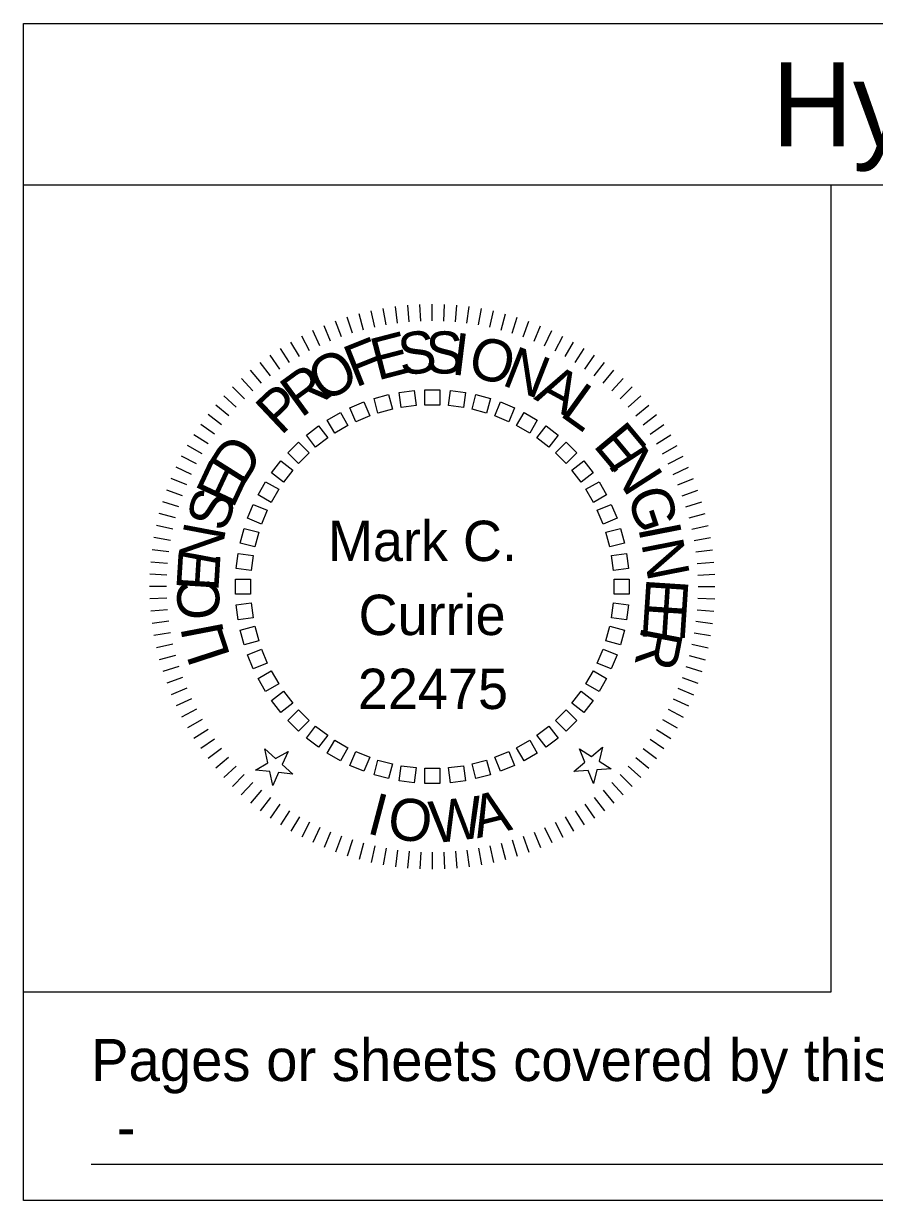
# Model space of a CAD drawing. Extents: x -0.84 to 4.97, y -1.01 to 2.42.
# Drawn here: x 4.3407 to 4.5514, y -0.9865 to -0.6948 of the extents above; entities that cross this region are included whole.
import ezdxf

# ---------------------------------------------------------------- set-up
doc = ezdxf.new("R2010")
doc.units = 0
for name, color, linetype in [('Level 1', 7, 'Continuous'), ('Level 2', 7, 'Continuous'), ('SheetGridMajor', 7, 'Continuous'), ('SheetGridMinor', 7, 'Continuous'), ('SheetText', 7, 'Continuous')]:
    doc.layers.add(name, color=color, linetype=linetype)

msp = doc.modelspace()

# ---------------------------------------------------------------- linework, layer by layer
at = {"layer": 'Level 1'}
for p, q in [((4.42489, -0.77078), (4.42381, -0.76675)), ((4.42768, -0.77009), (4.42678, -0.76603)), ((4.43049, -0.76953), (4.42977, -0.76543)), ((4.43333, -0.7691), (4.43279, -0.76497)), ((4.43619, -0.76878), (4.43583, -0.76463)), ((4.43906, -0.7686), (4.43887, -0.76443)), ((4.44193, -0.76853), (4.44193, -0.76437)), ((4.4448, -0.7686), (4.44498, -0.76443)), ((4.44766, -0.76878), (4.44803, -0.76463)), ((4.45052, -0.7691), (4.45106, -0.76497)), ((4.45336, -0.76953), (4.45408, -0.76543)), ((4.45618, -0.7701), (4.45708, -0.76603)), ((4.45897, -0.77078), (4.46004, -0.76675)), ((4.41673, -0.77355), (4.41514, -0.7697)), ((4.41941, -0.7725), (4.41799, -0.76859)), ((4.42213, -0.77158), (4.42088, -0.76761)), ((4.46172, -0.77158), (4.46298, -0.76761)), ((4.46444, -0.7725), (4.46587, -0.76859)), ((4.46712, -0.77355), (4.46871, -0.7697)), ((4.41153, -0.77597), (4.4096, -0.77228)), ((4.4141, -0.7747), (4.41234, -0.77093)), ((4.46975, -0.7747), (4.47151, -0.77093)), ((4.47232, -0.77597), (4.47425, -0.77228)), ((4.40655, -0.77884), (4.40432, -0.77533)), ((4.40901, -0.77735), (4.40693, -0.77375)), ((4.47484, -0.77735), (4.47693, -0.77375)), ((4.4773, -0.77884), (4.47954, -0.77533)), ((4.40417, -0.78044), (4.40178, -0.77703)), ((4.47969, -0.78044), (4.48208, -0.77703)), ((4.39961, -0.78394), (4.39693, -0.78074)), ((4.40185, -0.78214), (4.39931, -0.77883)), ((4.482, -0.78214), (4.48454, -0.77883)), ((4.48424, -0.78394), (4.48692, -0.78074)), ((4.39745, -0.78583), (4.39464, -0.78276)), ((4.4864, -0.78583), (4.48922, -0.78276)), ((4.39339, -0.78989), (4.39032, -0.78708)), ((4.39538, -0.78782), (4.39243, -0.78487)), ((4.48848, -0.78782), (4.49142, -0.78487)), ((4.49046, -0.78989), (4.49354, -0.78708)), ((4.3915, -0.79205), (4.3883, -0.78937)), ((4.49236, -0.79205), (4.49555, -0.78937)), ((4.3897, -0.79429), (4.38639, -0.79175)), ((4.49416, -0.79429), (4.49746, -0.79175)), ((4.388, -0.79661), (4.38459, -0.79422)), ((4.49585, -0.79661), (4.49927, -0.79422)), ((4.3864, -0.79899), (4.38289, -0.79676)), ((4.49745, -0.799), (4.50096, -0.79676)), ((4.38353, -0.80397), (4.37984, -0.80204)), ((4.38491, -0.80145), (4.38131, -0.79937)), ((4.49894, -0.80145), (4.50255, -0.79937)), ((4.50032, -0.80397), (4.50402, -0.80205)), ((4.38226, -0.80654), (4.37849, -0.80478)), ((4.50159, -0.80655), (4.50537, -0.80478)), ((4.3811, -0.80917), (4.37726, -0.80758)), ((4.50275, -0.80917), (4.5066, -0.80758)), ((4.38006, -0.81185), (4.37615, -0.81043)), ((4.50379, -0.81185), (4.5077, -0.81043)), ((4.37914, -0.81457), (4.37517, -0.81332)), ((4.50471, -0.81457), (4.50869, -0.81332)), ((4.37834, -0.81733), (4.37431, -0.81625)), ((4.50552, -0.81733), (4.50954, -0.81625)), ((4.37765, -0.82012), (4.37359, -0.81922)), ((4.5062, -0.82012), (4.51027, -0.81922)), ((4.37709, -0.82293), (4.37299, -0.82221)), ((4.50676, -0.82294), (4.51086, -0.82221)), ((4.37666, -0.82577), (4.37253, -0.82523)), ((4.5072, -0.82577), (4.51133, -0.82523)), ((4.37634, -0.82863), (4.37219, -0.82827)), ((4.50751, -0.82863), (4.51166, -0.82827)), ((4.37616, -0.8315), (4.37199, -0.83131)), ((4.5077, -0.8315), (4.51186, -0.83132)), ((4.37609, -0.83437), (4.37193, -0.83437)), ((4.50776, -0.83437), (4.51193, -0.83437)), ((4.37616, -0.83724), (4.37199, -0.83742)), ((4.5077, -0.83724), (4.51186, -0.83742)), ((4.37634, -0.84011), (4.37219, -0.84047)), ((4.50751, -0.84011), (4.51166, -0.84047)), ((4.37666, -0.84296), (4.37253, -0.84351)), ((4.37709, -0.8458), (4.37299, -0.84652)), ((4.50676, -0.8458), (4.51086, -0.84652)), ((4.5072, -0.84296), (4.51133, -0.84351)), ((4.37765, -0.84862), (4.37359, -0.84952)), ((4.5062, -0.84862), (4.51027, -0.84952)), ((4.37834, -0.85141), (4.37431, -0.85249)), ((4.50552, -0.85141), (4.50954, -0.85249)), ((4.37914, -0.85416), (4.37517, -0.85542)), ((4.50471, -0.85417), (4.50869, -0.85542)), ((4.38006, -0.85688), (4.37615, -0.85831)), ((4.50379, -0.85689), (4.5077, -0.85831)), ((4.3811, -0.85956), (4.37725, -0.86116)), ((4.50275, -0.85956), (4.5066, -0.86116)), ((4.38226, -0.86219), (4.37848, -0.86395)), ((4.50159, -0.86219), (4.50537, -0.86395)), ((4.38353, -0.86477), (4.37984, -0.86669)), ((4.50032, -0.86477), (4.50402, -0.86669)), ((4.38491, -0.86728), (4.3813, -0.86937)), ((4.49894, -0.86729), (4.50255, -0.86937)), ((4.3864, -0.86974), (4.38289, -0.87198)), ((4.49745, -0.86974), (4.50096, -0.87198)), ((4.388, -0.87213), (4.38459, -0.87452)), ((4.3897, -0.87445), (4.38639, -0.87698)), ((4.49415, -0.87445), (4.49746, -0.87698)), ((4.49585, -0.87213), (4.49927, -0.87452)), ((4.39149, -0.87669), (4.3883, -0.87936)), ((4.49236, -0.87669), (4.49555, -0.87936)), ((4.39339, -0.87884), (4.39032, -0.88166)), ((4.49046, -0.87885), (4.49353, -0.88166)), ((4.39537, -0.88092), (4.39243, -0.88387)), ((4.39745, -0.88291), (4.39463, -0.88598)), ((4.4864, -0.88291), (4.48922, -0.88598)), ((4.48848, -0.88092), (4.49142, -0.88387)), ((4.39961, -0.8848), (4.39693, -0.88799)), ((4.40185, -0.8866), (4.39931, -0.8899)), ((4.482, -0.8866), (4.48454, -0.8899)), ((4.48424, -0.8848), (4.48692, -0.88799)), ((4.40417, -0.8883), (4.40178, -0.89171)), ((4.47969, -0.8883), (4.48208, -0.89171)), ((4.40655, -0.88989), (4.40432, -0.89341)), ((4.40901, -0.89138), (4.40693, -0.89499)), ((4.47484, -0.89138), (4.47693, -0.89499)), ((4.4773, -0.88989), (4.47954, -0.89341)), ((4.41153, -0.89276), (4.4096, -0.89646)), ((4.4141, -0.89403), (4.41234, -0.89781)), ((4.41673, -0.89519), (4.41514, -0.89904)), ((4.46712, -0.89519), (4.46871, -0.89904)), ((4.46975, -0.89403), (4.47151, -0.89781)), ((4.47232, -0.89276), (4.47425, -0.89646)), ((4.41941, -0.89623), (4.41798, -0.90015)), ((4.42213, -0.89715), (4.42088, -0.90113)), ((4.42489, -0.89796), (4.42381, -0.90198)), ((4.45896, -0.89796), (4.46004, -0.90198)), ((4.46172, -0.89715), (4.46297, -0.90113)), ((4.46444, -0.89623), (4.46587, -0.90015)), ((4.42768, -0.89864), (4.42678, -0.90271)), ((4.43049, -0.8992), (4.42977, -0.9033)), ((4.43333, -0.89964), (4.43279, -0.90377)), ((4.43619, -0.89995), (4.43582, -0.9041)), ((4.43905, -0.90014), (4.43887, -0.9043)), ((4.44193, -0.9002), (4.44193, -0.90437)), ((4.4448, -0.90014), (4.44498, -0.9043)), ((4.44766, -0.89995), (4.44803, -0.9041)), ((4.45052, -0.89964), (4.45106, -0.90377)), ((4.45336, -0.8992), (4.45408, -0.90331)), ((4.45617, -0.89864), (4.45708, -0.90271))]:
    msp.add_line(p, q, dxfattribs=at)
for points in [[(4.43209, -0.79041), (4.42847, -0.79139), (4.4275, -0.78776), (4.43112, -0.78679)], [(4.43791, -0.78951), (4.43419, -0.79), (4.4337, -0.78628), (4.43742, -0.78579)], [(4.4438, -0.78937), (4.44005, -0.78937), (4.44005, -0.78562), (4.4438, -0.78562)], [(4.44966, -0.79), (4.44594, -0.78951), (4.44643, -0.78579), (4.45015, -0.78628)], [(4.45538, -0.79139), (4.45176, -0.79042), (4.45273, -0.78679), (4.45635, -0.78776)], [(4.42644, -0.79207), (4.42297, -0.79351), (4.42154, -0.79005), (4.425, -0.78861)], [(4.46088, -0.79351), (4.45741, -0.79208), (4.45885, -0.78861), (4.46231, -0.79005)], [(4.42105, -0.79446), (4.4178, -0.79633), (4.41593, -0.79309), (4.41917, -0.79121)], [(4.46605, -0.79633), (4.4628, -0.79446), (4.46468, -0.79121), (4.46792, -0.79309)], [(4.41602, -0.79752), (4.41304, -0.79981), (4.41076, -0.79683), (4.41374, -0.79455)], [(4.47081, -0.79981), (4.46783, -0.79752), (4.47012, -0.79455), (4.47309, -0.79683)], [(4.41143, -0.80122), (4.40878, -0.80387), (4.40613, -0.80122), (4.40878, -0.79857)], [(4.47507, -0.80387), (4.47242, -0.80122), (4.47507, -0.79857), (4.47772, -0.80122)], [(4.40737, -0.80549), (4.40508, -0.80846), (4.40211, -0.80618), (4.40439, -0.8032)], [(4.47877, -0.80846), (4.47649, -0.80549), (4.47946, -0.8032), (4.48174, -0.80618)], [(4.40389, -0.81024), (4.40202, -0.81349), (4.39877, -0.81162), (4.40064, -0.80837)], [(4.48184, -0.81349), (4.47996, -0.81024), (4.48321, -0.80837), (4.48508, -0.81162)], [(4.40107, -0.81541), (4.39963, -0.81888), (4.39617, -0.81744), (4.3976, -0.81398)], [(4.48422, -0.81888), (4.48278, -0.81541), (4.48625, -0.81398), (4.48768, -0.81744)], [(4.39894, -0.82091), (4.39797, -0.82453), (4.39435, -0.82356), (4.39532, -0.81994)], [(4.48588, -0.82453), (4.48491, -0.82091), (4.48853, -0.81994), (4.4895, -0.82356)], [(4.39756, -0.82663), (4.39707, -0.83035), (4.39335, -0.82986), (4.39384, -0.82615)], [(4.48679, -0.83035), (4.4863, -0.82663), (4.49001, -0.82614), (4.4905, -0.82986)], [(4.39693, -0.83249), (4.39693, -0.83624), (4.39318, -0.83624), (4.39318, -0.83249)], [(4.48693, -0.83624), (4.48693, -0.83249), (4.49068, -0.83249), (4.49068, -0.83624)], [(4.39707, -0.83838), (4.39756, -0.8421), (4.39384, -0.84259), (4.39335, -0.83887)], [(4.4863, -0.8421), (4.48679, -0.83838), (4.4905, -0.83887), (4.49001, -0.84259)], [(4.39797, -0.8442), (4.39895, -0.84783), (4.39532, -0.8488), (4.39435, -0.84518)], [(4.48491, -0.84783), (4.48588, -0.8442), (4.4895, -0.84518), (4.48853, -0.8488)], [(4.39963, -0.84986), (4.40107, -0.85332), (4.3976, -0.85476), (4.39617, -0.85129)], [(4.48278, -0.85332), (4.48422, -0.84986), (4.48768, -0.85129), (4.48625, -0.85476)], [(4.40202, -0.85524), (4.40389, -0.85849), (4.40064, -0.86037), (4.39877, -0.85712)], [(4.47996, -0.85849), (4.48183, -0.85524), (4.48508, -0.85712), (4.48321, -0.86037)], [(4.40508, -0.86028), (4.40737, -0.86325), (4.40439, -0.86553), (4.40211, -0.86256)], [(4.47649, -0.86325), (4.47877, -0.86027), (4.48174, -0.86256), (4.47946, -0.86553)], [(4.40878, -0.86486), (4.41143, -0.86751), (4.40878, -0.87017), (4.40613, -0.86751)], [(4.47242, -0.86751), (4.47507, -0.86486), (4.47772, -0.86751), (4.47507, -0.87017)], [(4.41304, -0.86893), (4.41602, -0.87121), (4.41374, -0.87419), (4.41076, -0.8719)], [(4.46783, -0.87121), (4.47081, -0.86893), (4.47309, -0.8719), (4.47012, -0.87419)], [(4.40049, -0.8746), (4.40313, -0.87697), (4.4062, -0.8752), (4.40476, -0.87844), (4.40739, -0.88081), (4.40386, -0.88044), (4.40242, -0.88368), (4.40169, -0.88021), (4.39816, -0.87984), (4.40123, -0.87806)], [(4.4178, -0.8724), (4.42105, -0.87428), (4.41917, -0.87753), (4.41593, -0.87565)], [(4.4628, -0.87428), (4.46605, -0.8724), (4.46793, -0.87565), (4.46468, -0.87752)], [(4.47834, -0.87458), (4.48135, -0.87646), (4.48407, -0.87418), (4.48321, -0.87762), (4.48621, -0.8795), (4.48268, -0.87975), (4.48182, -0.88319), (4.48049, -0.8799), (4.47695, -0.88015), (4.47967, -0.87787)], [(4.42297, -0.87523), (4.42644, -0.87666), (4.425, -0.88013), (4.42154, -0.87869)], [(4.42847, -0.87735), (4.43209, -0.87832), (4.43112, -0.88194), (4.4275, -0.88097)], [(4.45176, -0.87832), (4.45538, -0.87735), (4.45636, -0.88097), (4.45273, -0.88194)], [(4.45741, -0.87666), (4.46088, -0.87523), (4.46231, -0.87869), (4.45885, -0.88013)], [(4.43419, -0.87874), (4.43791, -0.87923), (4.43742, -0.88295), (4.4337, -0.88246)], [(4.44005, -0.87937), (4.4438, -0.87937), (4.4438, -0.88312), (4.44005, -0.88312)], [(4.44594, -0.87923), (4.44966, -0.87874), (4.45015, -0.88246), (4.44643, -0.88295)]]:
    msp.add_lwpolyline(points, close=True, dxfattribs=at)
at = {"layer": 'SheetGridMajor'}
for p, q in [((4.3407, -0.73482), (4.9657, -0.73482)), ((4.5407, -0.93482), (4.5407, -0.73482)), ((4.3407, -0.93482), (4.5407, -0.93482))]:
    msp.add_line(p, q, dxfattribs=at)
msp.add_lwpolyline([(4.3407, -0.69482), (4.9657, -0.69482), (4.9657, -0.98649), (4.3407, -0.98649)], close=True, dxfattribs=at)
at = {"layer": 'SheetGridMinor'}
msp.add_line((4.35742, -0.97751), (4.94904, -0.97751), dxfattribs=at)

# ---------------------------------------------------------------- texts
at = {"layer": 'Level 1'}
for s, rotation, p in [('F', 21.7736, (4.42287, -0.78511)), ('E', 14.5823, (4.42833, -0.78333)), ('S', 7.3911, (4.43418, -0.78212)), ('S', 0.1998, (4.44027, -0.78156)), ('I', 353.0085, (4.44638, -0.78171)), ('O', 345.8172, (4.45032, -0.78202)), ('N', 338.6259, (4.45885, -0.78428)), ('O', 28.9649, (4.41494, -0.78894)), ('R', 36.1562, (4.4094, -0.79272)), ('A', 331.4346, (4.46687, -0.78781)), ('L', 324.2434, (4.4732, -0.79181)), ('P', 43.3475, (4.40444, -0.79713)), ('E', 309.8608, (4.48152, -0.79939)), ('D', 57.7301, (4.39498, -0.80981)), ('N', 302.6695, (4.48524, -0.80407)), ('E', 64.9213, (4.39255, -0.81529)), ('S', 72.1126, (4.39071, -0.82113)), ('G', 288.2869, (4.48999, -0.81151)), ('N', 79.3039, (4.38905, -0.82975)), ('I', 281.0956, (4.49287, -0.81972)), ('N', 281.0956, (4.49363, -0.82359)), ('E', 86.4952, (4.38893, -0.83575)), ('C', 93.6865, (4.38952, -0.84233)), ('E', 266.2773, (4.495, -0.83207)), ('E', 266.2773, (4.49461, -0.83804)), ('I', 100.8778, (4.39042, -0.84618)), ('L', 108.069, (4.39199, -0.85159)), ('R', 259.086, (4.49386, -0.84396)), ('I', 345.2906, (4.42536, -0.89539)), ('O', 352.4819, (4.43046, -0.89663)), ('W', 6.8645, (4.44187, -0.89806)), ('A', 14.0557, (4.45304, -0.89677))]:
    msp.add_text(s, height=0.01042, rotation=rotation, dxfattribs=at).set_placement(p)
at = {"layer": 'Level 2'}
for s, p in [('Mark C.', (4.41609, -0.82803)), ('Currie', (4.42367, -0.84637)), ('22475', (4.42349, -0.8647))]:
    msp.add_text(s, height=0.01, dxfattribs=at).set_placement(p)
at = {"layer": 'SheetText'}
for s, height, p in [('Hydraulic Design', 0.0208333, (4.52596, -0.72524)), ('Pages or sheets covered by this seal:', 0.0104167, (4.35742, -0.95689)), ('-', 0.0104, (4.36379, -0.97349))]:
    msp.add_text(s, height=height, dxfattribs=at).set_placement(p)

doc.saveas('drawing.dxf')
